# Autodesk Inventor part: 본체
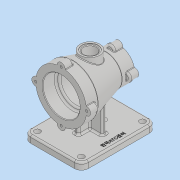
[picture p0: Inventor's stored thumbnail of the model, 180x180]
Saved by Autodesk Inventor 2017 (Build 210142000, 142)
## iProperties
Part Number: 본체
Material: 일반
Document SubType Name: Modeling
Designer: JiNi
Density: 1 g/cm^3
Appearance: 기본값
Author: JiNi
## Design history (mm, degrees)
sketch "스케치1"
  geometry: L1 (0, 44)-(20, 44); L2 (20, 44)-(78, 27.5); L3 (78, 27.5)-(100, 27.5); L4 (100, 27.5)-(100, 0); L5 (100, 0)-(0, 0); L6 (0, 0)-(0, 44)
  constraints: 12 end point, 3 perpendicular, 1 horizontal, 1 parallel
  dimensions: "d0" = 100 distance between parallel lines of L4 L6; "d1" = 20 distance of L1.start L1.end; "d2" = 88 diameter of L1 L5; "d3" = 55 diameter of L3 L5; "d4" = 22 distance of L2.end L3.end
revolve "회전1" sketch "스케치1" stored, may be unused: angle "d5" = 90 deg
hole "구멍1" diameter "d8" = 52; stored, may be unused: countersink angle "d12" = 90 deg, drill point angle "d14" = 0 deg; dims "d6" = 10, "d7" = 10, "d9" = 6, "d10" = 64, "d11" = 23, "d13" = 70
hole "구멍2" diameter "d17" = 40; stored, may be unused: countersink angle "d21" = 90 deg, drill point angle "d23" = 0 deg; dims "d15" = 10, "d16" = 10, "d18" = 6, "d19" = 64, "d20" = 23, "d22" = 5
node "작업 평면2"
sketch "스케치2"
  geometry: L1 (0, 44)-(0, -44) reference; C1 r 17 at (-50, 0); 1 further point
  constraints: 1 centre point, 1 horizontal alignment
  dimensions: "d26" = 34 diameter of C1; "d27" = 50 distance from line of C1.centre L1
extrude "돌출1" join sketch "스케치2" stored distance "d28" = 10; taper "d29" = 0 deg
node "작업 평면3"
sketch "스케치3"
  geometry: L1 (15, -50)-(-115, -50); L2 (-115, -50)-(-115, 50); L3 (-115, 50)-(15, 50); L4 (15, 50)-(15, -50); L5 (15, -50)-(-115, 50); L6 (-115, -50)-(15, 50); C1 r 17 at (-50, 0) reference; 1 further point
  constraints: 12 end point, 2 midpoint, 2 parallel, 1 horizontal, 1 perpendicular
  dimensions: "d31" = 130 distance of L2.end L3.end; "d32" = 100 distance of L1.end L2.end
extrude "돌출2" join sketch "스케치3" distance "d33" = 12; taper "d34" = 0 deg
sketch "스케치4"
  geometry: L1 (46, -25)-(54, -25); L2 (54, -25)-(54, 25); L3 (54, 25)-(46, 25); L4 (46, 25)-(46, -25); L5 (46, -25)-(54, 25); L6 (54, -25)-(46, 25); L7 (26, 4)-(74, 4); L8 (74, 4)-(74, -4); L9 (74, -4)-(26, -4); L10 (26, -4)-(26, 4); L11 (26, 4)-(74, -4); L12 (74, 4)-(26, -4); C1 r 17 at (50, 0) reference; 1 further point
  constraints: 24 end point, 4 midpoint, 4 parallel, 2 horizontal, 2 perpendicular
  dimensions: "d35" = 8 distance of L1.start L1.end; "d36" = 8 distance of L7.end L8.end; "d37" = 48 distance of L8.end L9.end; "d38" = 50 distance of L1.end L2.end
extrude "돌출3" join sketch "스케치4" stored distance "d39" = 12; taper "d40" = 0 deg
sketch "스케치5"
  geometry: C1 r 7 at (0, 44); 2 further points
  constraints: 2 vertical alignment, 1 centre point, 1 other
  dimensions: "d41" = 14 diameter of C1
extrude "돌출4" join sketch "스케치5" distance "d42" = 15; taper "d43" = 0 deg
hole "구멍3" diameter "d46" = 4.134; stored, may be unused: countersink angle "d50" = 90 deg, drill point angle "d52" = 118 deg; dims "d44" = 10, "d45" = 10, "d47" = 9, "d48" = 64, "d49" = 23, "d51" = 11
sketch "스케치6"
  geometry: C1 r 7 at (0, 27.5); 2 further points
  constraints: 2 vertical alignment, 1 centre point, 1 other
  dimensions: "d56" = 14 diameter of C1
extrude "돌출5" join sketch "스케치6" distance "d57" = 15; taper "d58" = 0 deg
hole "구멍4" diameter "d61" = 4.134; stored, may be unused: countersink angle "d65" = 90 deg, drill point angle "d67" = 118 deg; dims "d59" = 10, "d60" = 10, "d62" = 9, "d63" = 64, "d64" = 23, "d66" = 11
fillet "모깎기1" dims "d71" = 12
sketch "스케치7"
  geometry: L1 (-15, 38)-(-15, -38) reference; L2 (-3, -50)-(103, -50) reference; L3 (115, -38)-(115, 38) reference; L4 (103, 50)-(-3, 50) reference; L5 (54, -4)-(54, -25) reference; L6 (54, -25)-(46, -25) reference; L7 (46, -25)-(46, -4) reference; L8 (46, -4)-(26, -4) reference; L9 (26, -4)-(26, 4) reference; L10 (26, 4)-(46, 4) reference; L11 (46, 4)-(46, 25) reference; L12 (46, 25)-(54, 25) reference; L13 (54, 25)-(54, 4) reference; L14 (54, 4)-(74, 4) reference; L15 (74, 4)-(74, -4) reference; L16 (74, -4)-(54, -4) reference; A1 r 12 centre (-3, 38) between (-3, 50) and (-15, 38) reference; A2 r 12 centre (-3, -38) between (-15, -38) and (-3, -50) reference; A3 r 12 centre (103, -38) between (103, -50) and (115, -38) reference; A4 r 12 centre (103, 38) between (115, 38) and (103, 50) reference; 5 further points
  constraints: 4 coincident
hole "구멍5" sketch "스케치7" at (-3, 38), (103, 38), (103, -38), (-3, -38) diameter "d72" = 10; stored, may be unused: countersink angle "d76" = 90 deg, drill point angle "d78" = 118 deg; dims "d73" = 9, "d74" = 64, "d75" = 23, "d77" = 11
sketch "스케치8"
  geometry: L1 (103, -50)-(-3, -50) reference; L2 (-3, 50)-(103, 50) reference; 3 further points
  constraints: 1 midpoint, 1 vertical alignment, 1 other
  dimensions: "d79" = 10 distance from line of point (50, -40) L1
feature "엠보싱1" sketch "스케치8" dims "d0" = 100, "d1" = 20, "d2" = 88, "d3" = 55, "d4" = 22, "d80" = 0.5, "d81" = 0
hole "구멍6" diameter "d84" = 22; stored, may be unused: countersink angle "d88" = 90 deg, drill point angle "d90" = 0 deg; dims "d82" = 10, "d83" = 10, "d85" = 9, "d86" = 28, "d87" = 1, "d89" = 11
chamfer "모따기1" distance "d91" = 1; stored, may be unused: second distance "d92" = 2, angle "d93" = 45 deg
fillet "모깎기2" dims "d94" = 3
fillet "모깎기3" dims "d95" = 3
fillet "모깎기4" dims "d96" = 3
fillet "모깎기5" dims "d97" = 1
node "솔리드1"
pattern_circular "원형 패턴1" dims angle "d54" = 360 deg
pattern_circular "원형 패턴2" dims angle "d69" = 360 deg
node "투영된 루프1"
node "투영된 루프2"
other parameters: "d25" = 45, "d30" = -82
